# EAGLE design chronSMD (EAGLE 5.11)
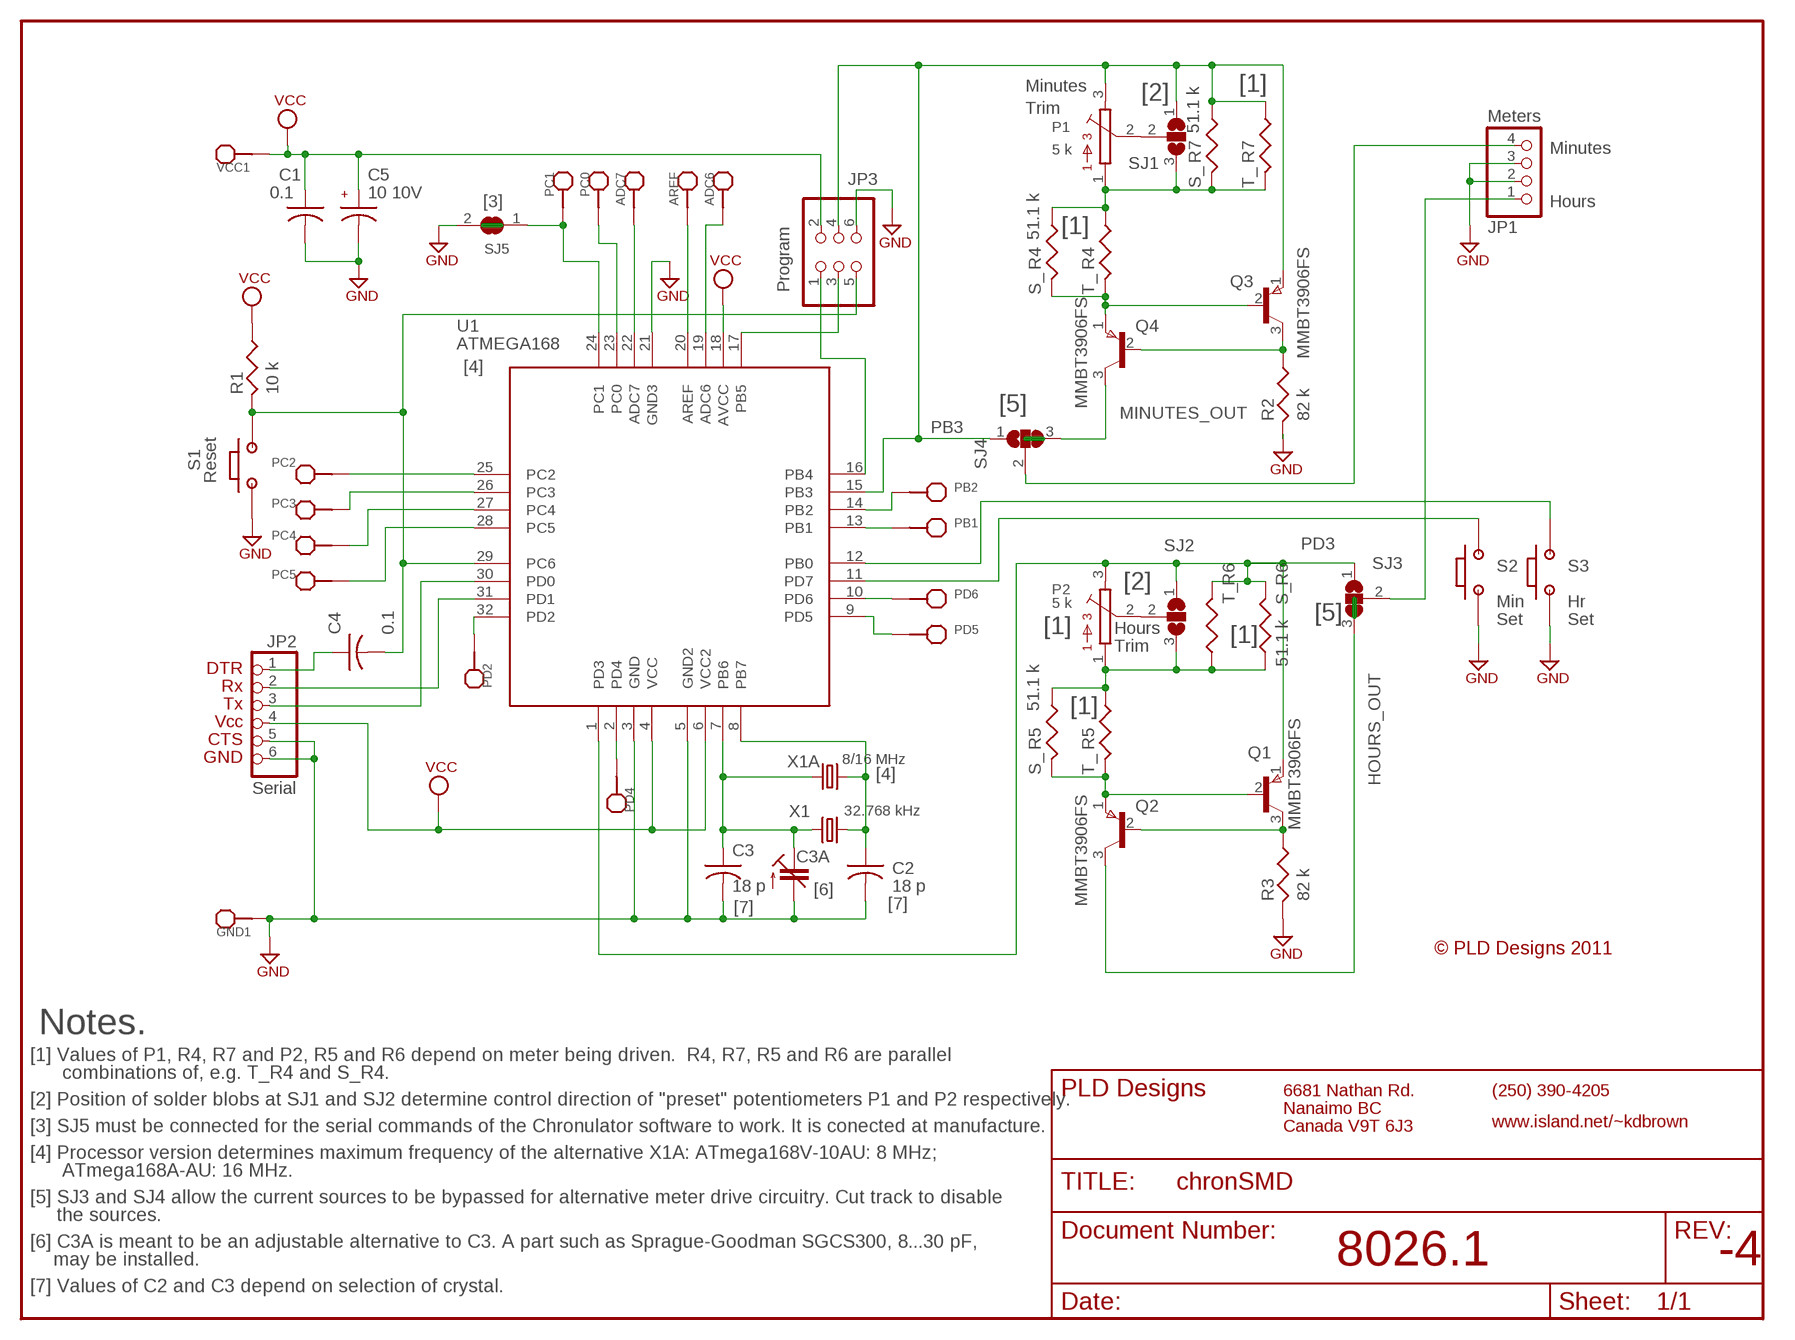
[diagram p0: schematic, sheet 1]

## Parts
ADC6  E0-NONE  E0-NONE@3  [E1-NONE]
ADC7  E0-NONE  E0-NONE@3  [E1-NONE]
AREF  E0-NONE  E0-NONE@3  [E1-NONE]
C1  0.1  C0805  [0805]
C2  18 p  C0603  [O603A]
C3  18 p  C0603  [O603A]
C3A  C-TRIMMCTZ2  [CTRIMCTZ2]
C4  0.1  C0805  [0805]
C5  10 10V  C3216  [CP3216]
GND1  E0-NONE  E0-NONE@2  [E2-NONE]
JP1  Meters  PINHD-1X4  [1X04SQ]
JP2  Serial  PINHD-1X6  [1X06SQ]
JP3  Program  PINHD-2X3  [2X03SQ]
P1  5 k  B25V  [B25V]
P2  5 k  B25V  [B25V]
PB1  E0-NONE  E0-NONE@3  [E1-NONE]
PB2  E0-NONE  E0-NONE@3  [E1-NONE]
PC0  E0-NONE  E0-NONE@3  [E1-NONE]
PC1  E0-NONE  E0-NONE@3  [E1-NONE]
PC2  E0-NONE  E0-NONE@3  [E1-NONE]
PC3  E0-NONE  E0-NONE@3  [E1-NONE]
PC4  E0-NONE  E0-NONE@3  [E1-NONE]
PC5  E0-NONE  E0-NONE@3  [E1-NONE]
PD2  E0-NONE  [E0-NONE]
PD4  E0-NONE  [E0-NONE]
PD5  E0-NONE  [E0-NONE]
PD6  E0-NONE  [E0-NONE]
Q1  MMBT3906FS  2N2906  [SOT-23R]
Q2  MMBT3906FS  2N2906  [SOT-23R]
Q3  MMBT3906FS  2N2906  [SOT-23R]
Q4  MMBT3906FS  2N2906  [SOT-23R]
R1  10 k  R0805  [0805]
R2  82 k  R0805  [0805]
R3  82 k  R0805  [0805]
R4  51.1 k  RCOMBO  [RCOMBO]
R5  51.1 k  RCOMBO  [RCOMBO]
R6  51.1 k  RCOMBO  [RCOMBO]
R7  51.1 k  RCOMBO  [RCOMBO]
S1  Reset  MINI-PB  [MINI-PB]
S2  Min  MINI-PB  [MINI-PB]
S3  Hr  MINI-PB  [MINI-PB]
SJ1  SJ2  [SJ2_8]
SJ2  x  SJ2  [SJ2_8]
SJ3  SJ2  [SJ2_8]
SJ4  SJ2  [SJ2_8]
SJ5  SJ  [SJ]
U1  ATMEGA168  ATMEGAX8  [TQFP-32]
VCC1  E0-NONE  E0-NONE@2  [E2-NONE]
X1  32.768 kHz  TC26H  [TC26H]
X1A  8/16 MHz  HC49/S  [HC49/S]

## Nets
ADC6: ADC6.P$1(E) U1.19(ADC6)
ADC7: ADC7.P$1(E) U1.22(ADC7)
AREF: AREF.P$1(E) U1.20(AREF)
GND: C1.2 C2.2 C3.2 C3A.2(A) C5.- GND1.P$1(E) JP1.2 JP1.3 JP2.5 JP2.6 JP3.6 R2.2 R3.2 S1.2 S2.2 S3.2 SJ5.2 U1.3(GND) U1.5(GND2) U1.21(GND3)
HOURS_OUT: Q2.3(C) SJ3.3
MINUTES_OUT: Q4.3(C) SJ4.3
N$1: C4.1 JP2.1
N$2: P1.2 SJ1.2
N$3: P2.2 SJ2.2
N$4: JP1.1 SJ3.2
N$5: JP1.4 SJ4.2
N$9: JP3.3 U1.17(PB5)
N$12: P1.1 R4.1 R4.4 R7.2 R7.3 SJ1.3
N$13: P2.1 R5.1 R5.4 R6.1 R6.4 SJ2.3
N$16: Q1.3(C) Q2.2(B) R3.1
N$17: Q1.2(B) Q2.1(E) R5.2 R5.3
N$18: Q3.3(C) Q4.2(B) R2.1
N$19: Q3.2(B) Q4.1(E) R4.2 R4.3
PB0: S3.1 U1.12(PB0)
PB1: PB1.P$1(E) U1.13(PB1)
PB2: PB2.P$1(E) U1.14(PB2)
PB3: JP3.4 P1.3 Q3.1(E) R7.1 R7.4 SJ1.1 SJ4.1 U1.15(PB3)
PB4: JP3.1 U1.16(PB4)
PB6: C3.1 C3A.1(E) U1.7(PB6) X1.2 X1A.1
PB7: C2.1 U1.8(PB7) X1.1 X1A.2
PC0: PC0.P$1(E) U1.23(PC0)
PC1: PC1.P$1(E) SJ5.1 U1.24(PC1)
PC2: PC2.P$1(E) U1.25(PC2)
PC3: PC3.P$1(E) U1.26(PC3)
PC4: PC4.P$1(E) U1.27(PC4)
PC5: PC5.P$1(E) U1.28(PC5)
PC6/RESET: C4.2 JP3.5 R1.2 S1.1 U1.29(PC6)
PD0: JP2.3 U1.30(PD0)
PD1: JP2.2 U1.31(PD1)
PD2: PD2.P$1(E) U1.32(PD2)
PD3: P2.3 Q1.1(E) R6.2 R6.3 SJ2.1 SJ3.1 U1.1(PD3)
PD4: PD4.P$1(E) U1.2(PD4)
PD5: PD5.P$1(E) U1.9(PD5)
PD6: PD6.P$1(E) U1.10(PD6)
PD7: S2.1 U1.11(PD7)
VCC: C1.1 C5.+ JP2.4 JP3.2 R1.1 U1.4(VCC) U1.6(VCC2) U1.18(AVCC) VCC1.P$1(E)

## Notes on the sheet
- Minutes | [1]
- [2]
- Trim
- Minutes
- [3] | Hours
- [1]
- [4]
- [5]
- [2]
- [5] | Set | Set
- [1] | Hours
- [1]
- Trim
- DTR
- Rx
- Tx | [1]
- Vcc
- CTS
- GND
- [4]
- [6] | [7]
- [7]
- © PLD Designs 2011
- Notes.
- [1] Values of P1, R4, R7 and P2, R5 and R6 depend on meter being driven.  R4, R7, R5 and R6 are parallel
- combinations of, e.g. T_R4 and S_R4.
- [2] Position of solder blobs at SJ1 and SJ2 determine control direction of "preset" potentiometers P1 and P2 respectively.
- [3] SJ5 must be connected for the serial commands of the Chronulator software to work. It is conected at manufacture.
- [4] Processor version determines maximum frequency of the alternative X1A: ATmega168V-10AU: 8 MHz;
- ATmega168A-AU: 16 MHz.
- [5] SJ3 and SJ4 allow the current sources to be bypassed for alternative meter drive circuitry. Cut track to disable
- the sources.
- [6] C3A is meant to be an adjustable alternative to C3. A part such as Sprague-Goodman SGCS300, 8...30 pF,
- may be installed. | 8026.1 | -4
- [7] Values of C2 and C3 depend on selection of crystal.

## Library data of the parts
ADC6 ADC7 AREF PB1 PB2 PC0 PC1-PC5 = PLDdesig:E0-NONE@3
C1 C4 = Discresi:C0805
C2 C3 = Discresi:C0603
C3A = rcl:C-TRIMM: Trimm capacitor
C5 = Discresi:C3216
GND1 VCC1 = PLDdesig:E0-NONE@2
JP1 = PINHEAD:PINHD-1X4
JP2 = PINHEAD:PINHD-1X6
JP3 = PINHEAD:PINHD-2X3
P1 P2 = TRIMPOT:B25V
PD2 PD4-PD6 = PLDdesig:E0-NONE
Q1-Q4 = PNP:2N2906
R1-R3 = Discresi:R0805
R4-R7 = heeb:RCOMBO
S1-S3 = Custom:MINI-PB
SJ1-SJ4 = JUMPER:SJ2
SJ5 = JUMPERpldd:SJ
U1 = Custom:ATMEGAX8
X1 = QUARTZ:TC26H
X1A = QUARTZ3_5:HC49/S

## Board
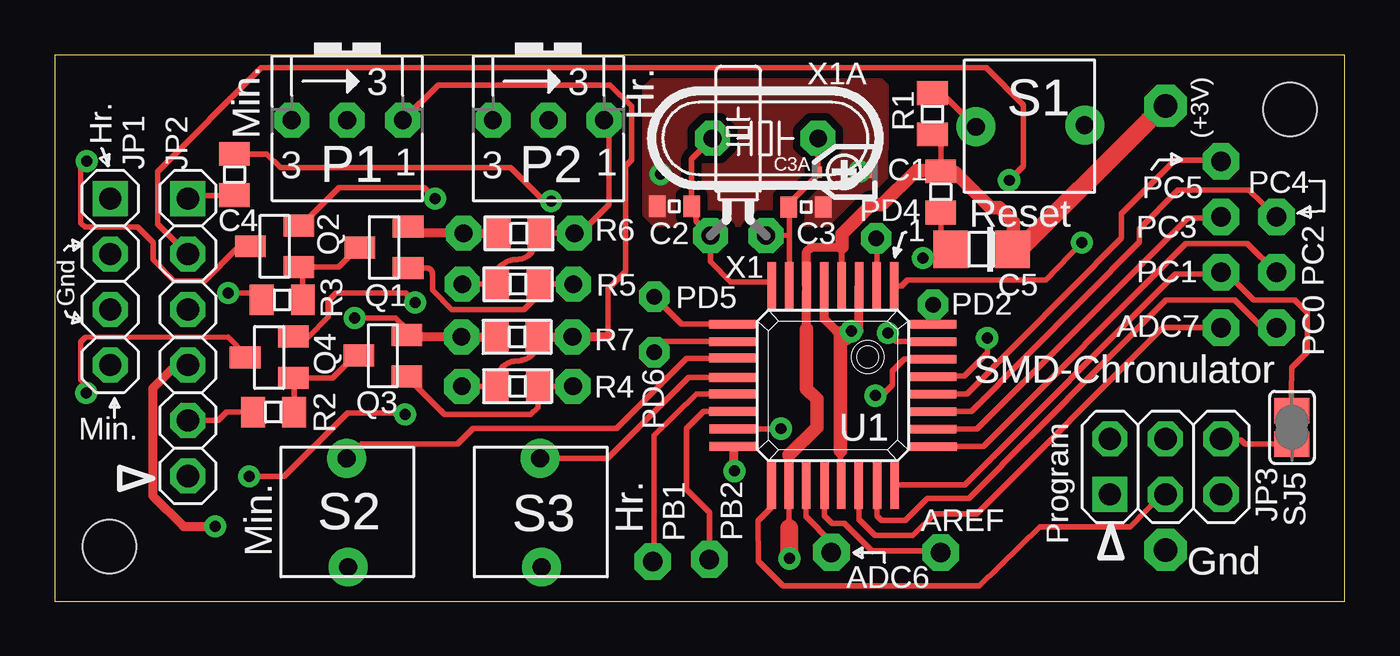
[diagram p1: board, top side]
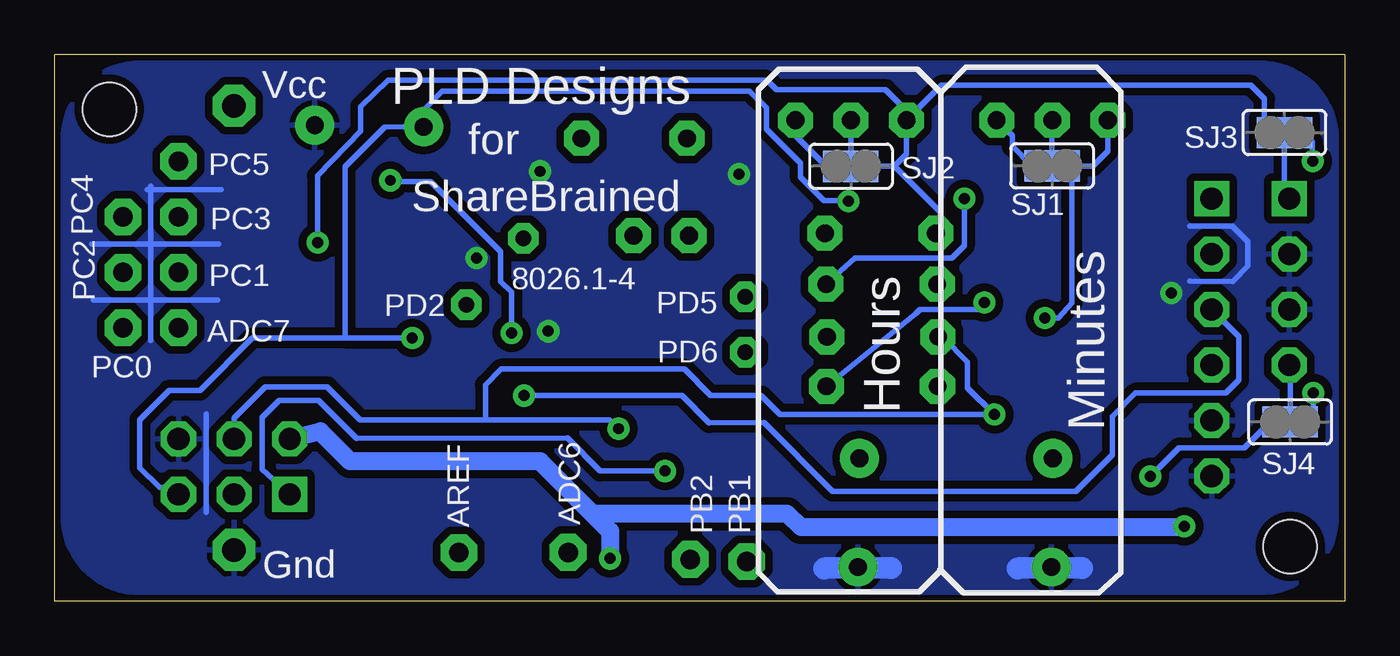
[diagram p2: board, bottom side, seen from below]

Size 59 x 25 mm. Coordinates in mm from the lower left corner, seen from the top.
Outline: 0,0 59,0 59,25 0,25 0,0
Copper layers (1*16): Top 0.035mm / dielectric 1.5mm / Bottom 0.035mm
Design rules "default *": minimum track width 10mil, minimum drill 18mil, track to track 8mil, track to pad 8mil, pad to pad 8mil, via to via 8mil, smd to smd 8mil, copper to edge 0mil, drill to drill 8mil, minimum pad ring 10mil, minimum via ring 10mil, stop-mask expansion 4mil, vias tented up to drill 0mil, thermal gap 10mil
Holes 2.44 mm at 56.5,22.5 2.5,2.5

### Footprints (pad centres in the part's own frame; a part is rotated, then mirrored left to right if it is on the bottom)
E1-NONE = drill 0.889 pad 1.676 octagon: P$1 0,0
0805 = smd 1.092 x 1.397: 1 -0.94,0; 2 0.94,0
O603A = smd 0.762 x 0.965: 1 -0.787,0; 2 0.787,0
CTRIMCTZ2 = smd 0.5 x 0.45: 1 0,1.25 | smd 0.55 x 0.5: 2 0,-1.25
CP3216 = smd 1.6 x 1.702: + -1.397,0; - 1.397,0
E2-NONE = drill 1.067 pad 1.93 octagon: P$1 0,0
1X04SQ = drill 1.016 pad 1.6 square: 1 -3.81,0 | drill 1.016 pad 1.6 octagon: 2 -1.27,0; 3 1.27,0; 4 3.81,0
1X06SQ = drill 1.016 pad 1.6 square: 1 -6.35,0 | drill 1.016 pad 1.6 octagon: 2 -3.81,0; 3 -1.27,0; 4 1.27,0; 5 3.81,0; 6 6.35,0
2X03SQ = drill 1.016 pad 1.6 square: 1 -2.54,-1.27 | drill 1.016 pad 1.6 octagon: 2 -2.54,1.27; 3 0,-1.27; 4 0,1.27; 5 2.54,-1.27; 6 2.54,1.27
B25V = drill 0.813 pad 1.6 octagon: 1 2.54,0; 2 0,0; 3 -2.54,0
E0-NONE = drill 0.711 pad 1.397 octagon: P$1 0,0
SOT-23R = smd 1 x 1.4: 1 0.95,-1.1; 2 -0.95,-1.1; 3 0,1.1
RCOMBO = smd 1.092 x 1.397: 1 0.94,0; 2 -0.94,0 | drill 0.813 pad 1.6 octagon: 3 -2.54,0; 4 2.54,0
MINI-PB = drill 0.813 pad 1.778 round: 1 2.45,0.033; 2 -2.523,-0.04
SJ2_8 = smd 0.711 x 1.422: 1 -0.914,0; 2 0,0; 3 0.914,0
SJ = smd 1.168 x 1.6: 1 -0.762,0; 2 0.762,0
TQFP-32 = smd 0.4 x 2.2: 1 -2.8,-4.55; 2 -2,-4.55; 3 -1.2,-4.55; 4 -0.4,-4.55; 5 0.4,-4.55; 6 1.2,-4.55; 7 2,-4.55; 8 2.8,-4.55; 17 2.81,4.56; 18 2.01,4.55; 19 1.22,4.54; 20 0.38,4.55; 21 -0.38,4.55; 22 -1.18,4.54; 23 -2.02,4.55; 24 -2.82,4.55 | smd 2.2 x 0.4: 9 4.56,-2.8; 10 4.57,-2; 11 4.57,-1.25; 12 4.56,-0.36; 13 4.56,0.39; 14 4.56,1.19; 15 4.55,1.99; 16 4.55,2.79; 25 -4.56,2.8; 26 -4.55,2; 27 -4.55,1.2; 28 -4.55,0.4; 29 -4.55,-0.4; 30 -4.55,-1.2; 31 -4.55,-2; 32 -4.55,-2.8
TC26H = drill 0.813 pad 1.6 octagon: 1 -1.27,0; 2 1.27,0
HC49/S = drill 0.813 pad 1.6 octagon: 1 -2.413,0; 2 2.413,0

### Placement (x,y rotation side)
ADC6  35.52,2.23 0 top
ADC7  53.34,12.5 0 top
AREF  40.52,2.22 0 top
C1  40.52,18.72 270 top
C2  28.34,18.06 180 top
C3  34.36,18.03 0 top
C3A  36.11,19.63 90 top
C4  8.23,19.52 90 top
C5  42.39,16.09 180 top
GND1  50.8,2.34 0 top
JP1  2.54,14.61 270 top
JP2  6.09,12.07 270 top
JP3  50.8,6.15 0 top
P1  13.38,22 0 top
P2  22.58,22 0 top
PB1  27.35,1.81 0 top
PB2  29.94,1.91 0 top
PC0  55.88,12.5 0 top
PC1  53.34,15.04 0 top
PC2  55.88,15.04 0 top
PC3  53.34,17.58 0 top
PC4  55.88,17.58 0 top
PC5  53.34,20.12 0 top
PD2  40.17,13.55 0 top
PD4  37.57,16.59 0 top
PD5  27.42,13.93 0 top
PD6  27.42,11.39 0 top
Q1  15.06,16.18 90 top
Q2  10.06,16.23 90 top
Q3  15.01,11.23 90 top
Q4  9.81,11.15 90 top
R1  40.14,22.29 90 top
R2  10.01,8.65 180 top
R3  10.41,13.78 180 top
R4  21.16,9.83 180 top
R5  21.18,14.5 180 top
R6  21.24,16.83 0 top
R7  21.14,12.09 180 top
S1  44.58,21.73 180 top
S2  13.38,4.08 90 top
S3  22.23,4.08 90 top
SJ1  13.39,19.91 180 bottom
SJ2  22.59,19.89 180 bottom
SJ3  2.76,21.44 0 bottom
SJ4  2.5,8.2 0 bottom
SJ5  56.58,7.95 270 top
U1  35.59,9.87 180 top
VCC1  50.8,22.66 0 top
X1  31.26,16.72 0 top
X1A  32.5,21.17 180 top

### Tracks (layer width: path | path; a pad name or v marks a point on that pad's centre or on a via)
ADC6
  Top 0.254: ADC6.P$1 35.52,2.7 34.35,3.87 34.35,5.3 U1.19
ADC7
  Top 0.254: U1.22 36.77,3.73 37.5,3 39.25,3 40.25,4 42.16,4 50.67,12.51 52.53,12.51 ADC7.P$1
AREF
  Top 0.254: U1.20 35.21,3.89 35.55,3.55 36.12,3.55 37.37,2.3 40.45,2.3 AREF.P$1 | AREF.P$1 40.55,2.2 | AREF.P$1
GND  (via drill 0.5 pad 1.02)
  Top 0.254: U1.3 36.79,12.39 36.74,12.35 | 35.22,14.42 35.25,14.45 | 35.22,14.42 U1.5 | 35.2,14.3 35.22,14.42 | v36.43,12.35 36.79,12.36 | C5.- 41.09,15.59 41.1,15.6 40.52,16.18 C1.2 | C2.2 27.34,18.06 | C3.2 34.95,18.05 35.36,18.05 35.36,18.4 | JP2.5 7.47,8.26 7.87,8.66 R2.2 | JP3.6 54.25,7.36 54.42,7.19 SJ5.2 | R3.2 9.16,14.09 v7.93,14.09 | U1.21 35.94,5.35 35.94,6.87
  Top 0.305: R2.2
  Top 0.406: 35.2,14.3 35.2,12.9 35.75,12.35 v36.43,12.35 36.74,12.35 | C5.- 40.98,15.7 v39.7,15.7 | 36.79,12.36 U1.3 | R2.2 9.07,8.63 9.1,8.6 | 35.94,12.09 36.12,12.09
  Top 0.61: 35.94,6.87 35.94,12.09
  Top 0.813: 36.12,12.09 v36.43,12.35
  Bottom 0.254: 7.08,17.16 5.13,17.16 5.13,17.13 4.44,16.44 4.44,15.32 5.13,14.63 7.08,14.64 | 51.51,16.33 57.3,16.33 | 51.54,13.77 57.24,13.77 | 54.61,11.92 54.61,18.99 | 51.4,18.82 54.77,18.82 | 52.06,4.07 52.06,8.57
  Bottom 1.016: 20.75,1.52 23.8,1.49 | 12.01,1.52 14.97,1.49
  other vias: 27.7,19.54 36.8,19.66
  pour Bottom (isolate 0.356): 4,24.6 arc95 0.4,21 0.4,4 arc95 4,0.4 55,0.4 arc95 58.6,4 58.6,21 arc95 55,24.6
  pour Top (isolate 0.356, no thermals): 37.55,17.25 27.45,17.25 27,17.7 27,23.45 27.45,23.9 37.67,23.9 38.02,23.55 38,17.7
HOURS_OUT  (via drill 0.5)
  Top 0.254: Q2.3 8.96,16.1 8.3,16.1 6.85,14.65 5.47,14.65 4.5,15.62 4.5,16.4 3.8,17.1 1.4,17.1 1.2,17.3 1.2,19.87 v1.46,20.13
  Bottom 0.254: v1.46,20.13 1.48,21.01 SJ3.3
MINUTES_OUT  (via drill 0.5)
  Top 0.254: Q4.3 8.67,11.33 7.92,12.07 1.4,12.07 1.19,11.85 1.18,10.12 1.18,10.11 1.44,9.85 v1.44,9.53
  Bottom 0.254: SJ4.3 1.49,8.41 1.44,8.46 v1.44,9.53
N$1
  Top 0.254: JP2.1 6.22,18.55 8.55,18.55
  Top 0.406: 8.55,18.55 C4.1
N$2
  Bottom 0.254: SJ1.2 P1.2
N$3
  Bottom 0.254: P2.2 22.58,21.98 22.59,21.97 SJ2.2
N$4
  Bottom 0.254: SJ3.2 2.76,18.54 JP1.1
N$5
  Bottom 0.254: SJ4.2 2.5,10.66 JP1.4
N$6
  Bottom 0.254: 1.76,21.45 2.78,21.45
N$8
  Top 0.254: 56.57,7.48 56.57,8.48
N$9
  Top 0.254: JP3.3 50.59,4.84 49.2,3.4 45.05,3.4 42.3,0.7 33.3,0.7 32.18,1.82 32.17,3.68 32.77,4.28 U1.17
N$10
  Bottom 0.254: 1.65,8.2 2.41,8.2
N$12
  Top 0.254: 25.3,12.11 25.3,14.27 26.1,15.07 26.1,19.91 26.37,20.18 26.37,22.64 25.4,23.61 17.53,23.61 P1.1 | 22.1,12.35 22.08,12.38 R7.2 | R7.2 22.1,12.07 | R7.2 22.1,12.1 | R4.4 R4.1 20.22,10.06 arc-90 21.15,10.99 arc90 22.08,11.92 R7.2 | R7.3 23.7,12.1 R7.3
  Top 0.406: R7.2 R7.3 | R7.3 25.3,12.1 25.3,12.11
  Bottom 0.254: P1.1 15.2,21.28 15.2,20.81 SJ1.3
N$13
  Top 0.254: P2.1 25.35,22 25.35,18.14 24.04,16.83 R6.4 R6.1 | R6.1 22,16.6 | R5.4 R5.1 20.11,14.65 arc-90 21.08,15.62 arc90 22.05,16.59 R6.1
  Bottom 0.254: SJ2.3 23.73,19.89 25.13,21.29 25.13,21.96 25.12,21.97 P2.1
N$16
  Top 0.254: R3.1 11.35,15.15 11.2,15.3 11.18,15.28 Q2.2 12.98,15.28 13.9,16.2 13.92,16.18 Q1.3
N$17  (via drill 0.5)
  Top 0.254: Q2.1 11.28,17.18 13,18.91 16.9,18.91 v17.4,18.41 | R5.3 R5.2 22.1,14.39 22.1,13.97 21.46,13.34 18.16,13.34 17.27,14.22 17.27,14.99 arc90 17.03,15.23 Q1.2
  Bottom 0.254: v17.4,18.41 17.4,16.26 17.97,15.68 22.41,15.68 R5.3
N$18
  Top 0.254: R2.1 10.95,10.15 Q4.2 12.7,10.2 13.8,11.3 13.87,11.23 Q3.3
N$19  (via drill 0.5)
  Top 0.254: Q3.2 16.49,9.9 16.49,9.89 17.84,8.54 21.77,8.54 22.1,8.87 R4.2 | Q4.1 11.61,12.09 12.5,12.99 12.5,13.72 12.88,14.1 16.05,14.1 v16.49,13.66 | R4.3 R4.2 | R4.2
  Bottom 0.254: v16.49,13.66 16.81,13.34 19.43,13.34 19.61,13.15 R4.3
PB0
  Top 0.254: 31.1,10.3 U1.12 28.98,10.23 25.28,6.53 S3.1
PB1
  Top 0.254: U1.13 29.34,9.48 27.4,7.59 27.4,1.8 27.39,1.81 PB1.P$1
PB2
  Top 0.254: U1.14 29.68,8.68 28.9,7.9 28.9,5.1 29.94,4.06 PB2.P$1
PB3  (via drill 0.5, 0.5 pad 1.02)
  Top 0.254: 18.99,12.09 19,12.1 | 16.21,12.09 16.2,12.1 16.4,12.1 16.3,12.2 16.28,12.18 Q3.1 16.11,12.45 15.6,12.96 v13.72,12.96 | v8.9,5.7 10.5,5.7 13.4,8.6 15.96,8.6 v16.02,8.54 | U1.15 v33.2,7.88 v33.21,7.89
  Top 0.406: R7.1 18.99,12.09 R7.4 16.21,12.09
  Bottom 0.254: 39.3,8.3 45.04,8.3 46.54,9.8 49.38,9.8 50.8,8.38 JP3.4 | v13.72,12.96 13.11,12.96 12.48,13.64 12.48,18.6 SJ1.1 11.52,19.91 10.84,20.58 P1.3 | R7.4 18.39,12.09 17.27,10.93 17.27,9.75 v16.02,8.54 25.84,8.54 26.7,9.4 29,9.4 30.19,10.61 38.59,10.61 39.3,9.9 39.3,8.3 | SJ4.1 4.6,7 7.6,7 v8.9,5.7 | 39.3,8.3 33.62,8.3 v33.21,7.89
PB4  (via drill 0.5 pad 1.02)
  Top 0.406: U1.16 31.04,6 v31.09,5.95
  Bottom 0.254: JP3.1 49.52,6.03 49.52,8.4 48.74,9.18 46.93,9.18 45.2,7.45 35.55,7.46 34.05,5.95 v31.09,5.95
PB6
  Top 0.127: 34.91,19.63 C3A.1
  Top 0.254: 33.37,18.17 C3.1 33.67,18.23 33.7,18.3 | U1.7 33.6,16.74 | 33.6,16.74 33.6,18.2 33.7,18.3 | 33.7,18.3 34.91,19.51 34.91,19.63 X1A.1 | X1.2 33.6,16.74
PB7
  Top 0.254: U1.8 32.61,14.6 30.9,14.6 29.98,15.53 29.98,16.47 X1.1 29.33,17.38 29.33,17.87 C2.1 29.13,20.21 X1A.2
PC0
  Top 0.254: U1.23 37.61,3.89 37.8,3.7 38.9,3.7 39.9,4.7 41.8,4.7 50.82,13.78 53.96,13.78 55.18,12.56 55.33,12.5 PC0.P$1
PC1
  Top 0.254: SJ5.1 56.55,9.48 56.57,10.68 57.27,11.39 57.27,13.21 56.7,13.78 54.84,13.78 53.58,15.04 PC1.P$1 52.46,14.96 51.26,14.96 41.62,5.32 U1.24
PC2
  Top 0.254: PC2.P$1 54.55,16.35 51.74,16.35 42.46,7.07 U1.25
PC3
  Top 0.254: U1.26 42.17,7.87 42.17,7.88 51.82,17.53 52.49,17.53 PC3.P$1
PC4
  Top 0.254: U1.27 41.92,8.67 49.6,16.41 49.6,17.02 51.37,18.8 54.61,18.8 PC4.P$1
PC5
  Top 0.254: U1.28 41.72,9.47 48.78,16.61 48.78,17.73 51.23,20.18 52.48,20.18 PC5.P$1
PC6/RESET  (via drill 0.5, 0.5 pad 1.02)
  Top 0.254: U1.29 39.73,10.27 39.7,10.3 41.6,10.3 42.65,11.35 v42.65,12.03 | R1.2 40.57,23.23 42.1,21.7 S1.1 | C4.2 9.69,20.46 10.34,19.83 20.84,19.83 22.35,18.32 v22.71,18.31
  Bottom 0.254: 45.73,12.04 v42.64,12.04 v42.65,12.03 42.73,12.03 | 45.73,12.04 49.96,12.03 52.35,9.64 53.77,9.64 55.1,8.3 55.1,6.1 54.2,5.2 52.77,5.2 JP3.5 | 45.73,12.04 45.72,19.87 43.92,21.69 43,21.7 S1.1 42.13,22.47 41.28,23.33 27.22,23.33 26.46,22.57 26.46,21.59 24.9,20.03 24.9,19.4 23.81,18.33 22.74,18.33 | 22.74,18.33 22.72,18.33 | v22.71,18.31 22.74,18.33
PD0  (via drill 0.5 pad 1.02)
  Top 0.254: v37.53,9.4 37.82,9.4 38.31,9.89 38.31,10.52 38.86,11.07 U1.30
  Bottom 0.254: v37.53,9.4 30.32,9.4 29.07,8.16 26.57,8.17 23.43,5.03 12.29,5.03 10.64,6.68 10.64,8.45 9.57,9.52 5.44,9.52 4.85,10.11 4.85,12.1 JP2.3
PD1  (via drill 0.5 pad 1.02)
  Top 0.254: v38.1,12.27 38.5,11.87 U1.31 | JP2.2 5.57,16.38 4.7,17.25 4.7,19.65 9.45,24.4 42.6,24.4 44.3,22.7 44.3,19.9 v43.65,19.25
  Bottom 0.254: v38.1,12.27 38.1,14.15 38.62,14.62 38.6,16 41.8,19.2 43.6,19.2 v43.65,19.25
PD2
  Top 0.254: U1.32 40.17,12.7 40.2,12.7 40.2,13.52 PD2.P$1
PD3  (via drill 0.5 pad 1.02)
  Top 0.254: U1.1 38.74,14.42 38.74,14.44 39,14.7 45.32,14.7 v46.98,16.4 | Q1.1 16.6,16.83
  Top 0.406: R6.2 R6.3 16.6,16.83
  Bottom 0.254: v46.98,16.4 46.98,19.46 45,21.49 45,22.62 43.76,23.83 26.43,23.83 26,23.4 21,23.4 20.04,22.44 P2.3 | R6.3 18.47,16.73 18.5,16.8 18.5,17.8 20.59,19.89 | 21.7,19.86 21.68,19.86 SJ2.1 20.59,19.89 | 20.59,19.89 20.04,20.44 P2.3 | SJ3.1 3.67,22.97 4.3,23.6 18.44,23.6 P2.3
PD4
  Top 0.254: PD4.P$1 37.53,16.65 37.6,16.65 U1.2
PD5
  Top 0.254: PD5.P$1 27.4,13.93 28.66,12.67 U1.9
PD6
  Top 0.254: PD6.P$1 27.4,11.39 27.4,11.87 U1.10
PD7
  Top 0.254: U1.11 31.08,11.12 31.1,11.1 28.9,11.1 25.7,7.9 19.13,7.9 18.43,7.2 14.03,7.2 S2.1
VCC  (via drill 0.5 pad 1.02)
  Top 0.254: 36,16.2 36,14.4 U1.4 35.99,15.89 | 33.58,2.84 U1.18 33.58,6.68 | 34.39,14.19 U1.6 | C1.1 40.46,19.66 40.4,19.6 40.3,19.7 | R1.1 40.2,21.4 40.52,21.08 C1.1 | 40.52,19.52 40.5,19.5 | C1.1 40.52,19.52 | 40.52,19.52 40.6,19.6
  Top 0.406: U1.6 34.39,15.99 34.6,16.2 36,16.2 | 34.39,12.45 34.39,14.19 | C5.+ 43.85,15.65 43.85,15.8 | 33.59,3.35 33.58,2.84 | JP2.4 5.55,10.8 4.5,9.75 4.5,4.8 5.89,3.42 v7.34,3.42
  Top 0.61: 33.58,6.68 34.86,7.95 34.86,9.25 34.39,9.71 34.39,12.45 | 36,16.2 36,16.8 37.34,18.14 37.84,18.14 39.4,19.7 40.3,19.7 | 43.85,15.8 43.85,17.35 43.2,18 42.8,18 41.2,19.6 40.6,19.6
  Top 0.813: VCC1.P$1 50.03,21.99 43.85,15.8 | v33.6,1.95 33.59,3.35
  Bottom 0.406: 33.6,3.2 33.6,3.3 | 24.87,3.38 25.08,3.38
  Bottom 0.813: v33.6,1.95 33.6,3.2 34.4,4 | 34.4,4 36.8,6.4 45.49,6.4 46.86,7.77 JP3.2 | 34.4,4 25.52,4 24.87,3.38 7.38,3.38 v7.34,3.42

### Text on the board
tNames: Hr. | Hr. | Min. | (+3V) | PC4 | PD4 | PC5 | PC3 | Reset | 1 | PC1 | PC0 | PC2 | Gnd | PD5 | PD2 | ADC7 | SMD-Chronulator | Min. | PD6 | Hr. | PB1 | PB2 | AREF | Program | Min. | ADC6 | Gnd
bNames: PLD Designs | Vcc | for | PC5 | ShareBrained | PC3 | PC4 | PD5 | 8026.1-4 | PC1 | PC2 | PD2 | PD6 | ADC7 | PC0 | Hours | Minutes | ADC6 | AREF | PB1 | PB2 | Gnd
_tNames: X1A | R1 | Hr. | S1 | Hr. | Min. | (+3V) | JP1 | JP2 | C3A | PC4 | P1 | P2 | C1 | C4 | PD4 | PC5 | PC3 | Reset | Q2 | R6 | C2 | C3 | 1 | PC1 | R3 | X1 | C5 | R5 | PC0 | PC2 | Gnd | Q1 | PD5 | PD2 | ADC7 | R7 | R2 | Q4 | SMD-Chronulator | Q3 | R4 | U1 | Min. | PD6 | JP3 | S2 | S3 | Hr. | PB1 | PB2 | AREF | Program | SJ5 | Min. | ADC6 | Gnd
_bNames: PLD Designs | Vcc | SJ3 | for | SJ2 | PC5 | SJ1 | ShareBrained | PC3 | PC4 | PD5 | 8026.1-4 | PC1 | PC2 | PD2 | PD6 | ADC7 | PC0 | Hours | Minutes | ADC6 | AREF | SJ4 | PB1 | PB2 | Gnd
